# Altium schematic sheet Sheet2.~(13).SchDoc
size A; SheetNumber: 1; SheetTotal: 1
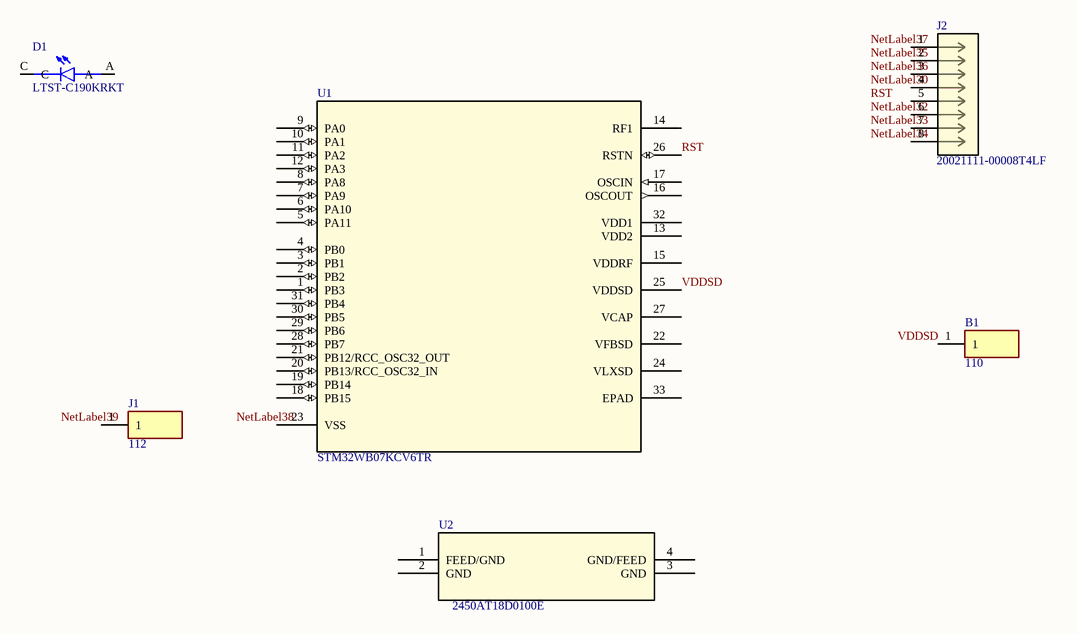
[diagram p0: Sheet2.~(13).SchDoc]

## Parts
B1  110  [110]
D1  LTST-C190KRKT  [LEDC1608X35N]
J1  112  [112]
J2  20021111-00008T4LF  [CONN_20021111-00008T4LF_AMP]
U1  STM32WB07KCV6TR  [VFQFPN-32_STM]
U2  2450AT18D0100E  [2450AT18D0100E_JOT]

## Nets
RST: U1.26(RSTN)
VDDSD: U1.25(VDDSD)

Not connected (* = marked no-connect by the designer): B1 1; D1 A C; J1 1; J2 1 2 3 4 5 6 7 8; U1 1(PB3) 2(PB2) 3(PB1) 4(PB0) 5(PA11) 6(PA10) 7(PA9) 8(PA8) 9(PA0) 10(PA1) 11(PA2) 12(PA3) 13(VDD2) 14(RF1) 15(VDDRF) 16(OSCOUT) 17(OSCIN) 18(PB15) 19(PB14) 20(PB13/RCC_OSC32_IN) 21(PB12/RCC_OSC32_OUT) 22(VFBSD) 23(VSS) 24(VLXSD) 27(VCAP) 28(PB7) 29(PB6) 30(PB5) 31(PB4) 32(VDD1) 33(EPAD); U2 1(FEED/GND) 2(GND) 3(GND) 4(GND/FEED)

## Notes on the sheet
- Labels drawn without touching a wire or pin: NetLabel30, NetLabel32, NetLabel33, NetLabel34, NetLabel35, NetLabel36, NetLabel37, NetLabel38, NetLabel39, RST, VDDSD

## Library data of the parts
B1 = 110: Battery Contacts S/M COIN CELL CNCT POSITIVE 16mm UP; Manufacturer_Name: Keystone Electronics; Geometry.Height: 3.3mm
D1 = LTST-C190KRKT: Red 631nm LED Indication - Discrete 2V 0603 (1608 Metric); MF: Lite-On Inc.
J1 = 112: Battery Contacts S/M COIN CELL CNCT NEGATIVE 16mm UP; Manufacturer_Name: Keystone Electronics; Geometry.Height: 3mm
J2 = 20021111-00008T4LF: No Description Available; Mfr_Name: Amphenol ICC
U1 = STM32WB07KCV6TR: Ultra-low-power, Arm Cortex-M0+ MCU 64 MHz with 256 Kbytes of Flash memory, 64 Kbytes of RAM,  Bluetooth LE 5.4; Manufacturer_Name: STMicroelectronics
U2 = 2450AT18D0100E: No Description Available; Manufacturer_Name: Johanson Technology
